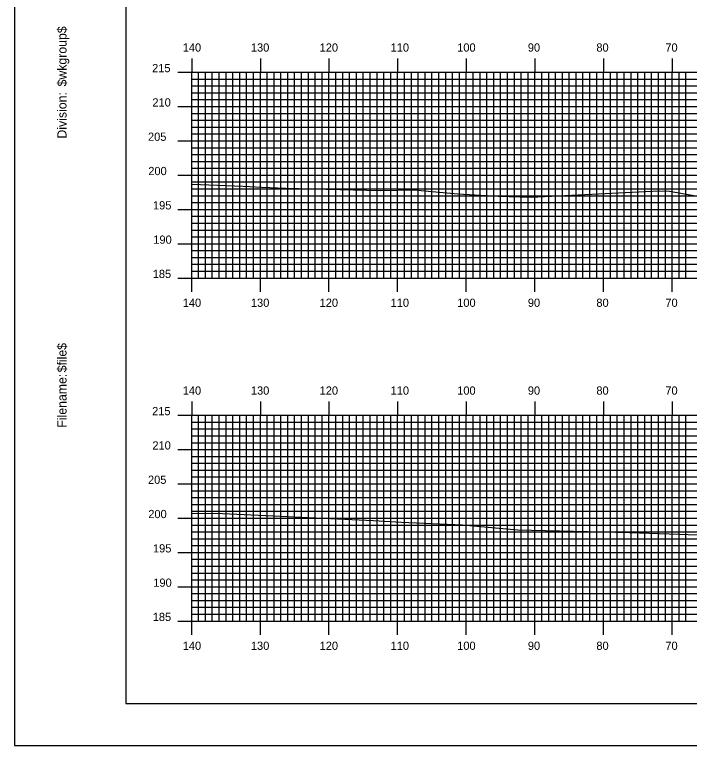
# Model space of a CAD drawing. Extents: x 1806651 to 1806995, y 442591 to 442811.
# Drawn here: x 1806651.5 to 1806749.7, y 442590.5 to 442697.1 of the extents above; entities that cross this region are included whole.
import ezdxf

# ---------------------------------------------------------------- set-up
doc = ezdxf.new("R2010")
doc.units = 0
for name, color, linetype in [('BORDER', 7, 'Continuous'), ('H_V ANNOTATION', 7, 'Continuous'), ('MAJOR', 7, 'Continuous'), ('MINOR', 7, 'Continuous'), ('PLOT BOUNDARY', 7, 'Continuous'), ('S_Roadway_Centerline', 7, 'Continuous')]:
    doc.layers.add(name, color=color, linetype=linetype)

msp = doc.modelspace()

# ---------------------------------------------------------------- linework, layer by layer
at = {"layer": 'BORDER'}
msp.add_lwpolyline([(1806667.65, 442596.67), (1806987.65, 442596.67), (1806987.65, 442806.67), (1806667.65, 442806.67)], close=True, dxfattribs=at)
at = {"layer": 'MAJOR'}
for p, q in [((1806677.25, 442690.67), (1806677.25, 442688.67)), ((1806687.25, 442690.67), (1806687.25, 442688.67)), ((1806697.25, 442690.67), (1806697.25, 442688.67)), ((1806707.25, 442690.67), (1806707.25, 442688.67)), ((1806717.25, 442690.67), (1806717.25, 442688.67)), ((1806727.25, 442690.67), (1806727.25, 442688.67)), ((1806737.25, 442690.67), (1806737.25, 442688.67)), ((1806747.25, 442690.67), (1806747.25, 442688.67)), ((1806675.24, 442688.67), (1806677.25, 442688.67)), ((1806677.25, 442688.67), (1806957.25, 442688.67)), ((1806677.25, 442658.67), (1806677.25, 442688.67)), ((1806677.25, 442658.67), (1806677.25, 442688.67)), ((1806677.25, 442688.67), (1806957.25, 442688.67)), ((1806687.25, 442658.67), (1806687.25, 442688.67)), ((1806697.25, 442658.67), (1806697.25, 442688.67)), ((1806707.25, 442658.67), (1806707.25, 442688.67)), ((1806717.25, 442658.67), (1806717.25, 442688.67)), ((1806727.25, 442658.67), (1806727.25, 442688.67)), ((1806737.25, 442658.67), (1806737.25, 442688.67)), ((1806747.25, 442658.67), (1806747.25, 442688.67)), ((1806675.24, 442683.67), (1806677.25, 442683.67)), ((1806677.25, 442683.67), (1806957.25, 442683.67)), ((1806675.24, 442678.67), (1806677.25, 442678.67)), ((1806677.25, 442678.67), (1806957.25, 442678.67)), ((1806675.24, 442673.67), (1806677.25, 442673.67)), ((1806677.25, 442673.67), (1806957.25, 442673.67)), ((1806675.24, 442668.67), (1806677.25, 442668.67)), ((1806677.25, 442668.67), (1806957.25, 442668.67)), ((1806675.24, 442663.67), (1806677.25, 442663.67)), ((1806677.25, 442663.67), (1806957.25, 442663.67)), ((1806675.24, 442658.67), (1806677.25, 442658.67)), ((1806677.25, 442658.67), (1806957.25, 442658.67)), ((1806677.25, 442658.67), (1806957.25, 442658.67)), ((1806677.25, 442656.66), (1806677.25, 442658.67)), ((1806687.25, 442656.66), (1806687.25, 442658.67)), ((1806697.25, 442656.66), (1806697.25, 442658.67)), ((1806707.25, 442656.66), (1806707.25, 442658.67)), ((1806717.25, 442656.66), (1806717.25, 442658.67)), ((1806727.25, 442656.66), (1806727.25, 442658.67)), ((1806737.25, 442656.66), (1806737.25, 442658.67)), ((1806747.25, 442656.66), (1806747.25, 442658.67)), ((1806677.25, 442640.67), (1806677.25, 442638.67)), ((1806687.25, 442640.67), (1806687.25, 442638.67)), ((1806697.25, 442640.67), (1806697.25, 442638.67)), ((1806707.25, 442640.67), (1806707.25, 442638.67)), ((1806717.25, 442640.67), (1806717.25, 442638.67)), ((1806727.25, 442640.67), (1806727.25, 442638.67)), ((1806737.25, 442640.67), (1806737.25, 442638.67)), ((1806747.25, 442640.67), (1806747.25, 442638.67)), ((1806675.24, 442638.67), (1806677.25, 442638.67)), ((1806677.25, 442638.67), (1806957.25, 442638.67)), ((1806677.25, 442608.67), (1806677.25, 442638.67)), ((1806677.25, 442608.67), (1806677.25, 442638.67)), ((1806677.25, 442638.67), (1806957.25, 442638.67)), ((1806687.25, 442608.67), (1806687.25, 442638.67)), ((1806697.25, 442608.67), (1806697.25, 442638.67)), ((1806707.25, 442608.67), (1806707.25, 442638.67)), ((1806717.25, 442608.67), (1806717.25, 442638.67)), ((1806727.25, 442608.67), (1806727.25, 442638.67)), ((1806737.25, 442608.67), (1806737.25, 442638.67)), ((1806747.25, 442608.67), (1806747.25, 442638.67)), ((1806675.24, 442633.67), (1806677.25, 442633.67)), ((1806677.25, 442633.67), (1806957.25, 442633.67)), ((1806675.24, 442628.67), (1806677.25, 442628.67)), ((1806677.25, 442628.67), (1806957.25, 442628.67)), ((1806675.24, 442623.67), (1806677.25, 442623.67)), ((1806677.25, 442623.67), (1806957.25, 442623.67)), ((1806675.24, 442618.67), (1806677.25, 442618.67)), ((1806677.25, 442618.67), (1806957.25, 442618.67)), ((1806675.24, 442613.67), (1806677.25, 442613.67)), ((1806677.25, 442613.67), (1806957.25, 442613.67)), ((1806675.24, 442608.67), (1806677.25, 442608.67)), ((1806677.25, 442608.67), (1806957.25, 442608.67)), ((1806677.25, 442608.67), (1806957.25, 442608.67)), ((1806677.25, 442606.66), (1806677.25, 442608.67)), ((1806687.25, 442606.66), (1806687.25, 442608.67)), ((1806697.25, 442606.66), (1806697.25, 442608.67)), ((1806707.25, 442606.66), (1806707.25, 442608.67)), ((1806717.25, 442606.66), (1806717.25, 442608.67)), ((1806727.25, 442606.66), (1806727.25, 442608.67)), ((1806737.25, 442606.66), (1806737.25, 442608.67)), ((1806747.25, 442606.66), (1806747.25, 442608.67))]:
    msp.add_line(p, q, dxfattribs=at)
at = {"layer": 'MINOR'}
for p, q in [((1806678.25, 442658.67), (1806678.25, 442688.67)), ((1806679.25, 442658.67), (1806679.25, 442688.67)), ((1806680.25, 442658.67), (1806680.25, 442688.67)), ((1806681.25, 442658.67), (1806681.25, 442688.67)), ((1806682.25, 442658.67), (1806682.25, 442688.67)), ((1806683.25, 442658.67), (1806683.25, 442688.67)), ((1806684.25, 442658.67), (1806684.25, 442688.67)), ((1806685.25, 442658.67), (1806685.25, 442688.67)), ((1806686.25, 442658.67), (1806686.25, 442688.67)), ((1806688.25, 442658.67), (1806688.25, 442688.67)), ((1806689.25, 442658.67), (1806689.25, 442688.67)), ((1806690.25, 442658.67), (1806690.25, 442688.67)), ((1806691.25, 442658.67), (1806691.25, 442688.67)), ((1806692.25, 442658.67), (1806692.25, 442688.67)), ((1806693.25, 442658.67), (1806693.25, 442688.67)), ((1806694.25, 442658.67), (1806694.25, 442688.67)), ((1806695.25, 442658.67), (1806695.25, 442688.67)), ((1806696.25, 442658.67), (1806696.25, 442688.67)), ((1806698.25, 442658.67), (1806698.25, 442688.67)), ((1806699.25, 442658.67), (1806699.25, 442688.67)), ((1806700.25, 442658.67), (1806700.25, 442688.67)), ((1806701.25, 442658.67), (1806701.25, 442688.67)), ((1806702.25, 442658.67), (1806702.25, 442688.67)), ((1806703.25, 442658.67), (1806703.25, 442688.67)), ((1806704.25, 442658.67), (1806704.25, 442688.67)), ((1806705.25, 442658.67), (1806705.25, 442688.67)), ((1806706.25, 442658.67), (1806706.25, 442688.67)), ((1806708.25, 442658.67), (1806708.25, 442688.67)), ((1806709.25, 442658.67), (1806709.25, 442688.67)), ((1806710.25, 442658.67), (1806710.25, 442688.67)), ((1806711.25, 442658.67), (1806711.25, 442688.67)), ((1806712.25, 442658.67), (1806712.25, 442688.67)), ((1806713.25, 442658.67), (1806713.25, 442688.67)), ((1806714.25, 442658.67), (1806714.25, 442688.67)), ((1806715.25, 442658.67), (1806715.25, 442688.67)), ((1806716.25, 442658.67), (1806716.25, 442688.67)), ((1806718.25, 442658.67), (1806718.25, 442688.67)), ((1806719.25, 442658.67), (1806719.25, 442688.67)), ((1806720.25, 442658.67), (1806720.25, 442688.67)), ((1806721.25, 442658.67), (1806721.25, 442688.67)), ((1806722.25, 442658.67), (1806722.25, 442688.67)), ((1806723.25, 442658.67), (1806723.25, 442688.67)), ((1806724.25, 442658.67), (1806724.25, 442688.67)), ((1806725.25, 442658.67), (1806725.25, 442688.67)), ((1806726.25, 442658.67), (1806726.25, 442688.67)), ((1806728.25, 442658.67), (1806728.25, 442688.67)), ((1806729.25, 442658.67), (1806729.25, 442688.67)), ((1806730.25, 442658.67), (1806730.25, 442688.67)), ((1806731.25, 442658.67), (1806731.25, 442688.67)), ((1806732.25, 442658.67), (1806732.25, 442688.67)), ((1806733.25, 442658.67), (1806733.25, 442688.67)), ((1806734.25, 442658.67), (1806734.25, 442688.67)), ((1806735.25, 442658.67), (1806735.25, 442688.67)), ((1806736.25, 442658.67), (1806736.25, 442688.67)), ((1806738.25, 442658.67), (1806738.25, 442688.67)), ((1806739.25, 442658.67), (1806739.25, 442688.67)), ((1806740.25, 442658.67), (1806740.25, 442688.67)), ((1806741.25, 442658.67), (1806741.25, 442688.67)), ((1806742.25, 442658.67), (1806742.25, 442688.67)), ((1806743.25, 442658.67), (1806743.25, 442688.67)), ((1806744.25, 442658.67), (1806744.25, 442688.67)), ((1806745.25, 442658.67), (1806745.25, 442688.67)), ((1806746.25, 442658.67), (1806746.25, 442688.67)), ((1806748.25, 442658.67), (1806748.25, 442688.67)), ((1806749.25, 442658.67), (1806749.25, 442688.67)), ((1806677.25, 442687.67), (1806957.25, 442687.67)), ((1806677.25, 442687.67), (1806679.25, 442687.67)), ((1806677.25, 442686.67), (1806957.25, 442686.67)), ((1806677.25, 442686.67), (1806679.25, 442686.67)), ((1806677.25, 442685.67), (1806957.25, 442685.67)), ((1806677.25, 442685.67), (1806679.25, 442685.67)), ((1806677.25, 442684.67), (1806957.25, 442684.67)), ((1806677.25, 442684.67), (1806679.25, 442684.67)), ((1806677.25, 442682.67), (1806957.25, 442682.67)), ((1806677.25, 442682.67), (1806679.25, 442682.67)), ((1806677.25, 442681.67), (1806957.25, 442681.67)), ((1806677.25, 442681.67), (1806679.25, 442681.67)), ((1806677.25, 442680.67), (1806957.25, 442680.67)), ((1806677.25, 442680.67), (1806679.25, 442680.67)), ((1806677.25, 442679.67), (1806957.25, 442679.67)), ((1806677.25, 442679.67), (1806679.25, 442679.67)), ((1806677.25, 442677.67), (1806957.25, 442677.67)), ((1806677.25, 442677.67), (1806679.25, 442677.67)), ((1806677.25, 442676.67), (1806957.25, 442676.67)), ((1806677.25, 442676.67), (1806679.25, 442676.67)), ((1806677.25, 442675.67), (1806957.25, 442675.67)), ((1806677.25, 442675.67), (1806679.25, 442675.67)), ((1806677.25, 442674.67), (1806957.25, 442674.67)), ((1806677.25, 442674.67), (1806679.25, 442674.67)), ((1806677.25, 442672.67), (1806957.25, 442672.67)), ((1806677.25, 442672.67), (1806679.25, 442672.67)), ((1806677.25, 442671.67), (1806957.25, 442671.67)), ((1806677.25, 442671.67), (1806679.25, 442671.67)), ((1806677.25, 442670.67), (1806957.25, 442670.67)), ((1806677.25, 442670.67), (1806679.25, 442670.67)), ((1806677.25, 442669.67), (1806957.25, 442669.67)), ((1806677.25, 442669.67), (1806679.25, 442669.67)), ((1806677.25, 442667.67), (1806957.25, 442667.67)), ((1806677.25, 442667.67), (1806679.25, 442667.67)), ((1806677.25, 442666.67), (1806957.25, 442666.67)), ((1806677.25, 442666.67), (1806679.25, 442666.67)), ((1806677.25, 442665.67), (1806957.25, 442665.67)), ((1806677.25, 442665.67), (1806679.25, 442665.67)), ((1806677.25, 442664.67), (1806957.25, 442664.67)), ((1806677.25, 442664.67), (1806679.25, 442664.67)), ((1806677.25, 442662.67), (1806957.25, 442662.67)), ((1806677.25, 442662.67), (1806679.25, 442662.67)), ((1806677.25, 442661.67), (1806957.25, 442661.67)), ((1806677.25, 442661.67), (1806679.25, 442661.67)), ((1806677.25, 442660.67), (1806957.25, 442660.67)), ((1806677.25, 442660.67), (1806679.25, 442660.67)), ((1806677.25, 442659.67), (1806957.25, 442659.67)), ((1806677.25, 442659.67), (1806679.25, 442659.67)), ((1806677.25, 442637.67), (1806957.25, 442637.67)), ((1806677.25, 442637.67), (1806679.25, 442637.67)), ((1806678.25, 442608.67), (1806678.25, 442638.67)), ((1806679.25, 442608.67), (1806679.25, 442638.67)), ((1806680.25, 442608.67), (1806680.25, 442638.67)), ((1806681.25, 442608.67), (1806681.25, 442638.67)), ((1806682.25, 442608.67), (1806682.25, 442638.67)), ((1806683.25, 442608.67), (1806683.25, 442638.67)), ((1806684.25, 442608.67), (1806684.25, 442638.67)), ((1806685.25, 442608.67), (1806685.25, 442638.67)), ((1806686.25, 442608.67), (1806686.25, 442638.67)), ((1806688.25, 442608.67), (1806688.25, 442638.67)), ((1806689.25, 442608.67), (1806689.25, 442638.67)), ((1806690.25, 442608.67), (1806690.25, 442638.67)), ((1806691.25, 442608.67), (1806691.25, 442638.67)), ((1806692.25, 442608.67), (1806692.25, 442638.67)), ((1806693.25, 442608.67), (1806693.25, 442638.67)), ((1806694.25, 442608.67), (1806694.25, 442638.67)), ((1806695.25, 442608.67), (1806695.25, 442638.67)), ((1806696.25, 442608.67), (1806696.25, 442638.67)), ((1806698.25, 442608.67), (1806698.25, 442638.67)), ((1806699.25, 442608.67), (1806699.25, 442638.67)), ((1806700.25, 442608.67), (1806700.25, 442638.67)), ((1806701.25, 442608.67), (1806701.25, 442638.67)), ((1806702.25, 442608.67), (1806702.25, 442638.67)), ((1806703.25, 442608.67), (1806703.25, 442638.67)), ((1806704.25, 442608.67), (1806704.25, 442638.67)), ((1806705.25, 442608.67), (1806705.25, 442638.67)), ((1806706.25, 442608.67), (1806706.25, 442638.67)), ((1806708.25, 442608.67), (1806708.25, 442638.67)), ((1806709.25, 442608.67), (1806709.25, 442638.67)), ((1806710.25, 442608.67), (1806710.25, 442638.67)), ((1806711.25, 442608.67), (1806711.25, 442638.67)), ((1806712.25, 442608.67), (1806712.25, 442638.67)), ((1806713.25, 442608.67), (1806713.25, 442638.67)), ((1806714.25, 442608.67), (1806714.25, 442638.67)), ((1806715.25, 442608.67), (1806715.25, 442638.67)), ((1806716.25, 442608.67), (1806716.25, 442638.67)), ((1806718.25, 442608.67), (1806718.25, 442638.67)), ((1806719.25, 442608.67), (1806719.25, 442638.67)), ((1806720.25, 442608.67), (1806720.25, 442638.67)), ((1806721.25, 442608.67), (1806721.25, 442638.67)), ((1806722.25, 442608.67), (1806722.25, 442638.67)), ((1806723.25, 442608.67), (1806723.25, 442638.67)), ((1806724.25, 442608.67), (1806724.25, 442638.67)), ((1806725.25, 442608.67), (1806725.25, 442638.67)), ((1806726.25, 442608.67), (1806726.25, 442638.67)), ((1806728.25, 442608.67), (1806728.25, 442638.67)), ((1806729.25, 442608.67), (1806729.25, 442638.67)), ((1806730.25, 442608.67), (1806730.25, 442638.67)), ((1806731.25, 442608.67), (1806731.25, 442638.67)), ((1806732.25, 442608.67), (1806732.25, 442638.67)), ((1806733.25, 442608.67), (1806733.25, 442638.67)), ((1806734.25, 442608.67), (1806734.25, 442638.67)), ((1806735.25, 442608.67), (1806735.25, 442638.67)), ((1806736.25, 442608.67), (1806736.25, 442638.67)), ((1806738.25, 442608.67), (1806738.25, 442638.67)), ((1806739.25, 442608.67), (1806739.25, 442638.67)), ((1806740.25, 442608.67), (1806740.25, 442638.67)), ((1806741.25, 442608.67), (1806741.25, 442638.67)), ((1806742.25, 442608.67), (1806742.25, 442638.67)), ((1806743.25, 442608.67), (1806743.25, 442638.67)), ((1806744.25, 442608.67), (1806744.25, 442638.67)), ((1806745.25, 442608.67), (1806745.25, 442638.67)), ((1806746.25, 442608.67), (1806746.25, 442638.67)), ((1806748.25, 442608.67), (1806748.25, 442638.67)), ((1806749.25, 442608.67), (1806749.25, 442638.67)), ((1806677.25, 442636.67), (1806957.25, 442636.67)), ((1806677.25, 442636.67), (1806679.25, 442636.67)), ((1806677.25, 442635.67), (1806957.25, 442635.67)), ((1806677.25, 442635.67), (1806679.25, 442635.67)), ((1806677.25, 442634.67), (1806957.25, 442634.67)), ((1806677.25, 442634.67), (1806679.25, 442634.67)), ((1806677.25, 442632.67), (1806957.25, 442632.67)), ((1806677.25, 442632.67), (1806679.25, 442632.67)), ((1806677.25, 442631.67), (1806957.25, 442631.67)), ((1806677.25, 442631.67), (1806679.25, 442631.67)), ((1806677.25, 442630.67), (1806957.25, 442630.67)), ((1806677.25, 442630.67), (1806679.25, 442630.67)), ((1806677.25, 442629.67), (1806957.25, 442629.67)), ((1806677.25, 442629.67), (1806679.25, 442629.67)), ((1806677.25, 442627.67), (1806957.25, 442627.67)), ((1806677.25, 442627.67), (1806679.25, 442627.67)), ((1806677.25, 442626.67), (1806957.25, 442626.67)), ((1806677.25, 442626.67), (1806679.25, 442626.67)), ((1806677.25, 442625.67), (1806957.25, 442625.67)), ((1806677.25, 442625.67), (1806679.25, 442625.67)), ((1806677.25, 442624.67), (1806957.25, 442624.67)), ((1806677.25, 442624.67), (1806679.25, 442624.67)), ((1806677.25, 442622.67), (1806957.25, 442622.67)), ((1806677.25, 442622.67), (1806679.25, 442622.67)), ((1806677.25, 442621.67), (1806957.25, 442621.67)), ((1806677.25, 442621.67), (1806679.25, 442621.67)), ((1806677.25, 442620.67), (1806957.25, 442620.67)), ((1806677.25, 442620.67), (1806679.25, 442620.67)), ((1806677.25, 442619.67), (1806957.25, 442619.67)), ((1806677.25, 442619.67), (1806679.25, 442619.67)), ((1806677.25, 442617.67), (1806957.25, 442617.67)), ((1806677.25, 442617.67), (1806679.25, 442617.67)), ((1806677.25, 442616.67), (1806957.25, 442616.67)), ((1806677.25, 442616.67), (1806679.25, 442616.67)), ((1806677.25, 442615.67), (1806957.25, 442615.67)), ((1806677.25, 442615.67), (1806679.25, 442615.67)), ((1806677.25, 442614.67), (1806957.25, 442614.67)), ((1806677.25, 442614.67), (1806679.25, 442614.67)), ((1806677.25, 442612.67), (1806957.25, 442612.67)), ((1806677.25, 442612.67), (1806679.25, 442612.67)), ((1806677.25, 442611.67), (1806957.25, 442611.67)), ((1806677.25, 442611.67), (1806679.25, 442611.67)), ((1806677.25, 442610.67), (1806957.25, 442610.67)), ((1806677.25, 442610.67), (1806679.25, 442610.67)), ((1806677.25, 442609.67), (1806957.25, 442609.67)), ((1806677.25, 442609.67), (1806679.25, 442609.67))]:
    msp.add_line(p, q, dxfattribs=at)
at = {"layer": 'PLOT BOUNDARY'}
msp.add_lwpolyline([(1806651.46, 442590.55), (1806991.46, 442590.55), (1806991.46, 442810.55), (1806651.46, 442810.55)], close=True, dxfattribs=at)
at = {"layer": 'S_Roadway_Centerline'}
for points in [[(1806677.25, 442672.37), (1806684.73, 442672.07), (1806687.47, 442671.9), (1806690.93, 442671.77), (1806704.73, 442671.41), (1806709.62, 442671.54), (1806716.01, 442670.95), (1806721.87, 442670.62), (1806726.71, 442670.48), (1806743.37, 442671.29), (1806745.42, 442671.38), (1806746.85, 442671.31), (1806756.4, 442669.65), (1806767.22, 442668.99), (1806770.17, 442668.75), (1806779.58, 442668.51), (1806789.98, 442668.67), (1806791.6, 442668.68), (1806812.38, 442668.09), (1806815.02, 442668.06), (1806821.89, 442667.95), (1806856.56, 442667.51)], [(1806677.25, 442624.4), (1806681.74, 442624.35), (1806703.74, 442623.32), (1806707.77, 442623.07), (1806716.71, 442622.69), (1806724.73, 442621.95), (1806741, 442621.6), (1806746.81, 442621.39), (1806752.32, 442621.2), (1806758.61, 442621.12), (1806768.42, 442620.77), (1806775.2, 442620.42), (1806786.38, 442620.3), (1806788.14, 442620.27), (1806789.37, 442620.21), (1806791.37, 442620.08), (1806821.28, 442618.56), (1806831.23, 442618.46), (1806833.22, 442618.41), (1806835.26, 442618.46), (1806853.24, 442618.41)]]:
    msp.add_lwpolyline(points, dxfattribs=at)

# ---------------------------------------------------------------- texts
at = {"layer": 'BORDER'}
for s, p in [('$wkgroup$', (1806659.02, 442686.6)), ('Division:', (1806659.02, 442679)), ('$file$', (1806659.02, 442644.92)), ('Filename:', (1806659.02, 442636.86))]:
    msp.add_text(s, height=1.339, rotation=90, dxfattribs=at).set_placement(p)
at = {"layer": 'H_V ANNOTATION'}
for s, p in [('140', (1806675.95, 442691.67)), ('130', (1806685.88, 442691.67)), ('120', (1806695.89, 442691.67)), ('110', (1806706.23, 442691.67)), ('100', (1806715.93, 442691.67)), ('90', (1806726.22, 442691.67)), ('80', (1806736.2, 442691.67)), ('70', (1806746.25, 442691.67)), ('215', (1806671.49, 442688.67)), ('210', (1806671.53, 442683.67)), ('205', (1806670.89, 442678.67)), ('200', (1806670.93, 442673.67)), ('195', (1806671.62, 442668.67)), ('190', (1806671.66, 442663.67)), ('185', (1806671.58, 442658.67)), ('140', (1806675.95, 442654.47)), ('130', (1806685.88, 442654.47)), ('120', (1806695.89, 442654.47)), ('110', (1806706.23, 442654.47)), ('100', (1806715.93, 442654.47)), ('90', (1806726.22, 442654.47)), ('80', (1806736.2, 442654.47)), ('70', (1806746.25, 442654.47)), ('140', (1806675.95, 442641.67)), ('130', (1806685.88, 442641.67)), ('120', (1806695.89, 442641.67)), ('110', (1806706.23, 442641.67)), ('100', (1806715.93, 442641.67)), ('90', (1806726.22, 442641.67)), ('80', (1806736.2, 442641.67)), ('70', (1806746.25, 442641.67)), ('215', (1806671.49, 442638.67)), ('210', (1806671.53, 442633.67)), ('205', (1806670.89, 442628.67)), ('200', (1806670.93, 442623.67)), ('195', (1806671.62, 442618.67)), ('190', (1806671.66, 442613.67)), ('185', (1806671.58, 442608.67)), ('140', (1806675.95, 442604.47)), ('130', (1806685.88, 442604.47)), ('120', (1806695.89, 442604.47)), ('110', (1806706.23, 442604.47)), ('100', (1806715.93, 442604.47)), ('90', (1806726.22, 442604.47)), ('80', (1806736.2, 442604.47)), ('70', (1806746.25, 442604.47))]:
    msp.add_text(s, height=1.2, dxfattribs=at).set_placement(p)
at = {"layer": 'MAJOR'}
for p in [(1806677.24, 442658.67), (1806677.24, 442608.67)]:
    msp.add_text('-', height=0.012, dxfattribs=at).set_placement(p)

doc.saveas('drawing.dxf')
